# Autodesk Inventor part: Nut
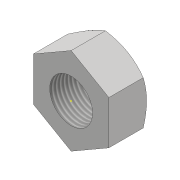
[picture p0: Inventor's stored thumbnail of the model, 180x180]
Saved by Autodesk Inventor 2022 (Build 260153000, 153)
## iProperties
Created: 2016-05
Part Number: Nut
Material: Generic
Document SubType Name: Modeling
Designer: CADCIM
Density: 1 g/cm^3
Appearance: Default
Author: CADCIM
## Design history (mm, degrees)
sketch "Sketch1"
  geometry: L1 (0, -33.255)-(-28.8, -16.628); L2 (-28.8, -16.628)-(-28.8, 16.628); L3 (-28.8, 16.628)-(0, 33.255); L4 (0, 33.255)-(28.8, 16.628); L5 (28.8, 16.628)-(28.8, -16.628); L6 (28.8, -16.628)-(0, -33.255); 2 further points
  constraints: 12 end point, 1 coincident, 13 other
  dimensions: "d0" = 57.6 distance between parallel lines of L2 L5
extrude "Extrusion1" new body sketch "Sketch1" stored distance "d1" = 28.8; taper "d2" = 0 deg
sketch "Sketch2"
  geometry: L1 (0, 33.255)-(-28.8, 16.628) reference; C1 r 28.8 at (0, 0); 1 further point
  constraints: 1 centre point, 1 coincident, 1 tangent
extrude "Extrusion2" sketch "Sketch2" distance "d3" = 28.8; taper "d4" = 60 deg
sketch "Sketch3"
  geometry: 1 further point
hole "Hole1" diameter "d7" = 32.752; stored, may be unused: countersink angle "d11" = 90 deg, drill point angle "d13" = 118 deg; dims "d5" = 10, "d6" = 10, "d8" = 72, "d9" = 4, "d10" = 2, "d12" = 85.1
body "Solid1"
